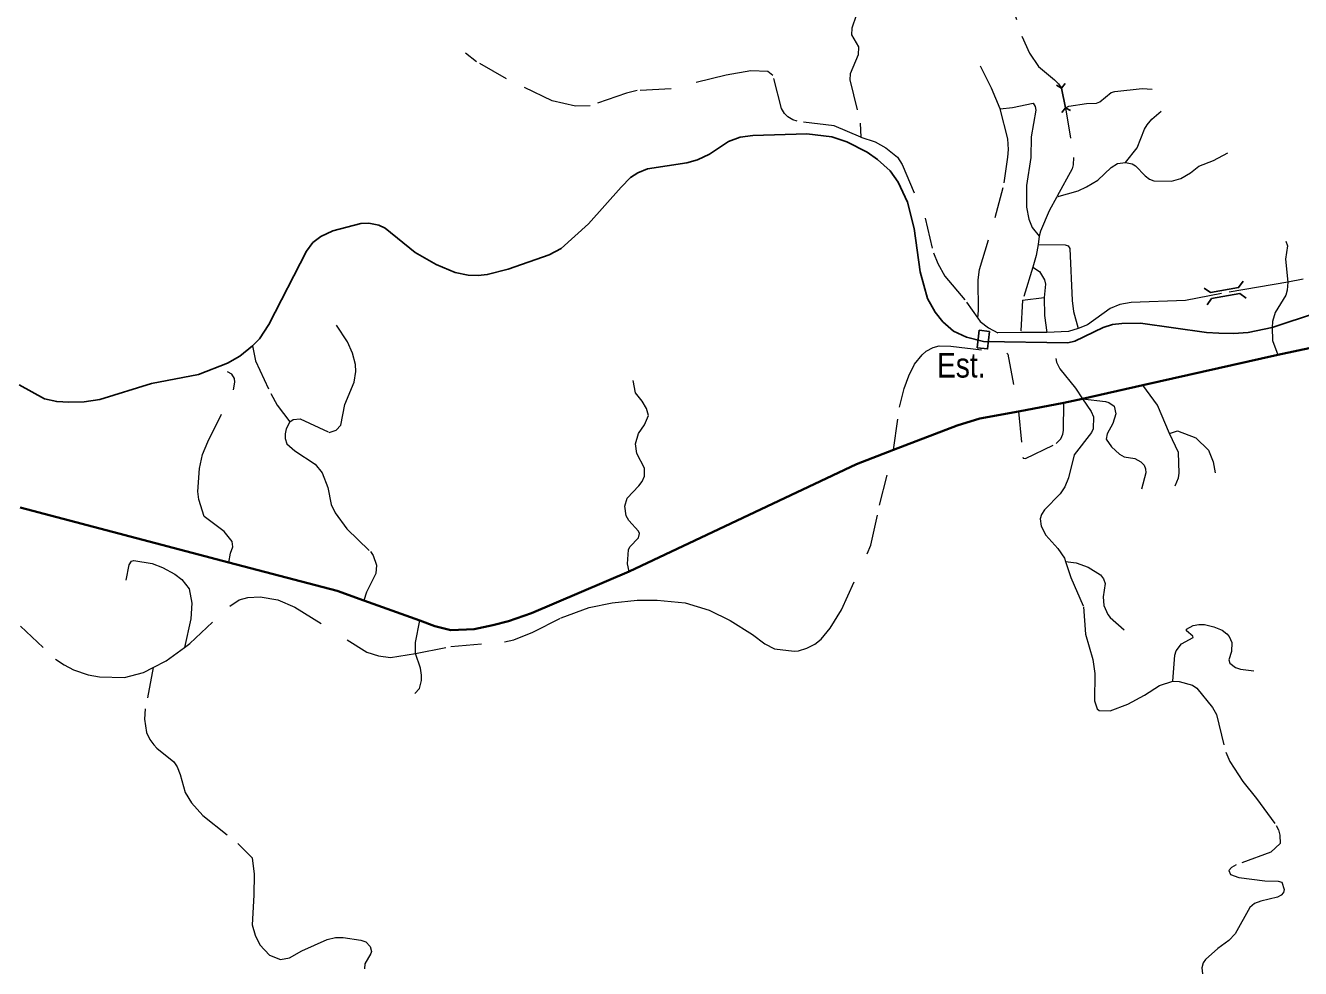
# Model space of a CAD drawing. Extents: x 220.8 to 246.7, y 7287.6 to 7315.8.
# Drawn here: x 235.279 to 239.405, y 7305.147 to 7308.198 of the extents above; entities that cross this region are included whole.
import ezdxf
from ezdxf.enums import TextEntityAlignment as Align

# ---------------------------------------------------------------- set-up
doc = ezdxf.new("R2010")
doc.units = 0
doc.header["$LTSCALE"] = 0.032
for name, pattern in [('DOTTED', [1.5, 0.3, -1.2]), ('LONG_DASHED', [7.5, 6, -1.5]), ('MEDIUM_DASHED', [4.5, 3, -1.5])]:
    doc.linetypes.add(name, pattern=pattern)
for name, color, linetype, lineweight in [('10', 7, 'Continuous', 25), ('15', 7, 'Continuous', 25), ('2', 7, 'Continuous', 35), ('28', 7, 'Continuous', 25), ('31', 7, 'Continuous', 25), ('5', 7, 'LONG_DASHED', 13), ('6', 7, 'MEDIUM_DASHED', 13), ('7', 7, 'DOTTED', 13)]:
    doc.layers.add(name, color=color, linetype=linetype, lineweight=lineweight)
doc.layers.add('61', color=7, linetype='Continuous')

msp = doc.modelspace()

# ---------------------------------------------------------------- linework, layer by layer
at = {"layer": '10'}
for p, q in [((239.1133, 7307.3343), (239.0929, 7307.3487)), ((239.1026, 7307.2942), (239.1168, 7307.3146)), ((239.1168, 7307.3146), (239.2078, 7307.3307)), ((239.2284, 7307.3165), (239.2078, 7307.3307))]:
    msp.add_line(p, q, dxfattribs=at)
msp.add_lwpolyline([(239.1133, 7307.3343), (239.2043, 7307.3504), (239.2187, 7307.371)], dxfattribs=at)
at = {"layer": '15'}
msp.add_lwpolyline([(239.7468, 7307.3643), (239.3125, 7307.2206), (239.235, 7307.2054), (239.188, 7307.2019), (239.1401, 7307.2028), (239.0999, 7307.2045), (238.8872, 7307.2353), (238.8265, 7307.2344), (238.7966, 7307.231), (238.7658, 7307.2207), (238.6744, 7307.1772), (238.6513, 7307.1712), (238.3787, 7307.1763), (238.324, 7307.19), (238.2821, 7307.2096), (238.2471, 7307.2395), (238.2223, 7307.2703), (238.1975, 7307.3147), (238.1736, 7307.4011), (238.1539, 7307.5412), (238.1326, 7307.6267), (238.1027, 7307.6916), (238.077, 7307.7284), (238.036, 7307.7651), (238.0027, 7307.789), (237.9369, 7307.8224), (237.8882, 7307.8386), (237.807, 7307.848), (237.6327, 7307.8429), (237.5916, 7307.8369), (237.554, 7307.8232), (237.4917, 7307.7822), (237.4532, 7307.7642), (237.419, 7307.754), (237.2917, 7307.7343), (237.2601, 7307.7215), (237.237, 7307.7061), (237.2062, 7307.6754), (237.1011, 7307.5566), (237.0123, 7307.4763), (236.9729, 7307.4558), (236.8405, 7307.4096), (236.773, 7307.3925), (236.7439, 7307.3891), (236.7114, 7307.3908), (236.6687, 7307.3993), (236.6072, 7307.425), (236.5397, 7307.4634), (236.4431, 7307.5421), (236.4218, 7307.5523), (236.3893, 7307.5583), (236.3636, 7307.5574), (236.2731, 7307.5335), (236.2346, 7307.5156), (236.209, 7307.4959), (236.1876, 7307.4677), (236.0663, 7307.231), (236.0355, 7307.184), (236.013, 7307.1615), (235.9723, 7307.1285), (235.9329, 7307.1054), (235.8389, 7307.0695), (235.686, 7307.0396), (235.5193, 7306.9883), (235.4681, 7306.9806), (235.4185, 7306.9798), (235.38, 7306.9815), (235.3399, 7306.99), (235.2578, 7307.0353)], dxfattribs=at)
at = {"layer": '2'}
msp.add_lwpolyline([(235.2612, 7306.6381), (235.937, 7306.461), (236.2872, 7306.3691), (236.3741, 7306.3378), (236.5552, 7306.2724), (236.6035, 7306.255), (236.6546, 7306.2419), (236.7307, 7306.2445), (236.7911, 7306.2576), (236.8422, 7306.2707), (236.9157, 7306.297), (237.2323, 7306.4315), (237.968, 7306.7785), (238.088, 7306.825), (238.2934, 7306.9045), (238.3669, 7306.9268), (238.4921, 7306.9497), (238.6391, 7306.9774), (238.699, 7306.9905), (238.6995, 7306.9906), (238.8939, 7307.0343), (239.3316, 7307.1323), (239.6303, 7307.1959)], dxfattribs=at)
at = {"layer": '28'}
msp.add_lwpolyline([(238.3985, 7307.2085), (238.3921, 7307.1519), (238.3584, 7307.1557), (238.3648, 7307.2123)], close=True, dxfattribs=at)
at = {"layer": '31'}
for p, q in [((238.6312, 7307.9957), (238.6428, 7308.0105)), ((238.6151, 7308.0051), (238.6312, 7307.9957)), ((238.6312, 7307.9957), (238.6437, 7307.9321)), ((238.6321, 7307.9174), (238.6437, 7307.9321)), ((238.6437, 7307.9321), (238.6599, 7307.9228))]:
    msp.add_line(p, q, dxfattribs=at)
at = {"layer": '5'}
for points in [[(238.5556, 7307.4901), (238.6431, 7307.4881), (238.6531, 7307.4851), (238.6582, 7307.477), (238.6652, 7307.308), (238.6702, 7307.2728), (238.6854, 7307.218)], [(239.8673, 7307.477), (239.7828, 7307.4479), (239.7003, 7307.4298), (239.3631, 7307.368), (239.1492, 7307.3307), (239.0324, 7307.308), (238.8563, 7307.302), (238.8201, 7307.296), (238.789, 7307.2829), (238.7155, 7307.2296), (238.6854, 7307.218)], [(238.6854, 7307.218), (238.6542, 7307.2085), (238.5836, 7307.2054), (238.4992, 7307.2054), (238.4248, 7307.2034)]]:
    msp.add_lwpolyline(points, dxfattribs=at)
at = {"layer": '6'}
for p, q in [((238.5384, 7307.4168), (238.5055, 7307.3096)), ((238.5055, 7307.3096), (238.4992, 7307.2054)), ((238.5055, 7307.3096), (238.5754, 7307.3181))]:
    msp.add_line(p, q, dxfattribs=at)
for points in [[(238.0208, 7308.4066), (238.0204, 7308.3112), (238.0054, 7308.2784), (237.9666, 7308.2306), (237.9532, 7308.1903), (237.9517, 7308.1686), (237.9748, 7308.129), (237.9733, 7308.1037), (237.9472, 7308.0417), (237.9465, 7308.0223), (237.9801, 7307.8827), (237.9823, 7307.8371)], [(238.4553, 7308.3135), (238.5031, 7308.1644), (238.5272, 7308.109), (238.5573, 7308.0652), (238.6088, 7308.0224), (238.621, 7308.01), (238.6312, 7307.9957), (238.6437, 7307.9321), (238.6702, 7307.7708), (238.6691, 7307.7478), (238.6658, 7307.7341), (238.6159, 7307.6438), (238.5913, 7307.5987), (238.5628, 7307.5324), (238.559, 7307.5165), (238.5556, 7307.4901), (238.5496, 7307.454), (238.5384, 7307.4168)], [(237.9823, 7307.8371), (237.8957, 7307.8737), (237.7762, 7307.8886), (237.7613, 7307.8931), (237.7456, 7307.9028), (237.7344, 7307.914), (237.7254, 7307.9297), (237.6971, 7308.0365), (237.6814, 7308.0492), (237.6254, 7308.0514), (237.5463, 7308.038), (237.3678, 7307.9932), (237.258, 7307.9879), (237.2237, 7307.9797), (237.1057, 7307.9387), (237.0587, 7307.9372), (236.9833, 7307.9543), (236.8354, 7308.0253), (236.7384, 7308.0813), (236.7025, 7308.1089)], [(237.9823, 7307.8371), (238.0278, 7307.8214), (238.0629, 7307.802), (238.1003, 7307.7721), (238.1152, 7307.7483), (238.1899, 7307.575), (238.2168, 7307.4623), (238.2309, 7307.4279), (238.2533, 7307.3869), (238.3243, 7307.3032), (238.3601, 7307.2514), (238.3683, 7307.2405), (238.3945, 7307.2196), (238.4248, 7307.2034)], [(238.5384, 7307.4168), (238.5595, 7307.4025), (238.5765, 7307.3756), (238.5798, 7307.3614), (238.5754, 7307.3181)], [(238.5754, 7307.3181), (238.576, 7307.26), (238.5836, 7307.2054)], [(235.2626, 7306.2541), (235.376, 7306.1482), (235.4036, 7306.1292), (235.4341, 7306.1136), (235.4819, 7306.0975), (235.5181, 7306.0906), (235.5987, 7306.0889), (235.6609, 7306.105), (235.692, 7306.121), (235.7334, 7306.1424), (235.7929, 7306.186), (235.8105, 7306.1988), (235.94, 7306.3197), (235.9699, 7306.3398), (235.9987, 7306.3473), (236.0378, 7306.3496), (236.0948, 7306.3398), (236.1506, 7306.3162), (236.3831, 7306.1706), (236.4206, 7306.1585), (236.4597, 7306.1533), (236.541, 7306.1665), (236.6548, 7306.189), (236.8286, 7306.2034), (236.8591, 7306.2103), (236.9207, 7306.2351), (237.0116, 7306.2811), (237.1031, 7306.3145), (237.1774, 7306.33), (237.2585, 7306.3387), (237.3224, 7306.3387), (237.4139, 7306.33), (237.491, 7306.3064), (237.5589, 7306.2725), (237.6314, 7306.2276), (237.6711, 7306.1971), (237.7028, 7306.181), (237.7661, 7306.1741), (237.7805, 7306.1746), (237.807, 7306.1839), (237.8329, 7306.1965), (237.853, 7306.2126), (237.8824, 7306.2483), (237.9192, 7306.307), (238.0147, 7306.5165), (238.0424, 7306.646), (238.088, 7306.825), (238.1068, 7306.9637), (238.1218, 7307.0241), (238.1373, 7307.0644), (238.1557, 7307.1029), (238.1805, 7307.1323), (238.1931, 7307.145), (238.2162, 7307.1559), (238.2357, 7307.1616), (238.2731, 7307.1611), (238.4538, 7307.1381), (238.4573, 7307.1352), (238.4921, 7306.9497), (238.5062, 7306.8014), (238.5074, 7306.7979), (238.5143, 7306.7968), (238.6144, 7306.8457), (238.6288, 7306.8607), (238.6357, 7306.8756), (238.6374, 7306.8883), (238.6391, 7306.9774)], [(238.6124, 7307.1211), (238.6146, 7307.109), (238.626, 7307.087), (238.676, 7307.0248), (238.6989, 7306.9907), (238.699, 7306.9905), (238.7268, 7306.9498), (238.7344, 7306.9324), (238.7336, 7306.8929), (238.7283, 7306.8808), (238.6722, 7306.8088), (238.6541, 7306.7345), (238.6419, 7306.7057), (238.6268, 7306.683), (238.576, 7306.6315), (238.5661, 7306.6163), (238.5623, 7306.6019), (238.5654, 7306.5784), (238.5805, 7306.5489), (238.6192, 7306.5057), (238.6404, 7306.4746), (238.6439, 7306.4639), (238.6609, 7306.4117), (238.7026, 7306.3169), (238.7094, 7306.229), (238.7329, 7306.1472), (238.7389, 7306.1009), (238.7381, 7306.0127), (238.7465, 7305.9872), (238.7526, 7305.9819), (238.7882, 7305.9804), (238.8458, 7306.0024), (238.8996, 7306.0312), (238.9481, 7306.063), (238.991, 7306.0768), (239.0125, 7306.0752), (239.055, 7306.0638), (239.0694, 7306.0539), (239.1194, 7305.991), (239.1331, 7305.9683), (239.1626, 7305.8463), (239.1755, 7305.8167), (239.2179, 7305.7523), (239.2627, 7305.697), (239.3256, 7305.6098), (239.3339, 7305.5954), (239.3377, 7305.578), (239.3385, 7305.5514), (239.3089, 7305.5234), (239.1967, 7305.4825), (239.1808, 7305.4741), (239.1732, 7305.4635), (239.1778, 7305.4514), (239.2051, 7305.4408), (239.2892, 7305.4309), (239.3324, 7305.4294), (239.3438, 7305.4256), (239.3513, 7305.4029), (239.3498, 7305.3923), (239.3422, 7305.3839), (239.3301, 7305.3771), (239.2763, 7305.3642), (239.2558, 7305.3566), (239.2407, 7305.3445), (239.1937, 7305.2589), (239.1725, 7305.2369), (239.1368, 7305.2119), (239.0967, 7305.1763), (239.0891, 7305.1649), (239.0853, 7305.149), (239.0876, 7305.13)]]:
    msp.add_lwpolyline(points, dxfattribs=at)
at = {"layer": '7'}
for points in [[(238.4326, 7307.9288), (238.4049, 7307.9961), (238.3691, 7308.0663)], [(238.6437, 7307.9321), (238.6551, 7307.937), (238.7122, 7307.9463), (238.7441, 7307.9468), (238.7548, 7307.9513), (238.7923, 7307.9815), (238.804, 7307.9849), (238.8919, 7307.995), (238.9244, 7307.9927)], [(238.3601, 7307.2514), (238.3631, 7307.2764), (238.3616, 7307.3757), (238.3661, 7307.4093), (238.4169, 7307.5773), (238.446, 7307.6893), (238.4572, 7307.7721), (238.4594, 7307.7968), (238.4572, 7307.8319), (238.4326, 7307.9288)], [(238.4326, 7307.9288), (238.4729, 7307.9334), (238.5393, 7307.9469), (238.546, 7307.9364), (238.5483, 7307.9245), (238.5326, 7307.8379), (238.5318, 7307.7707), (238.5184, 7307.6811), (238.5177, 7307.6101), (238.5251, 7307.5713), (238.5363, 7307.5444), (238.559, 7307.5165)], [(238.8387, 7307.7548), (238.8757, 7307.8024), (238.8998, 7307.8634), (238.9081, 7307.8768), (238.9238, 7307.8953), (238.9535, 7307.9216)], [(238.8387, 7307.7548), (238.86, 7307.7503), (238.8706, 7307.7447), (238.902, 7307.7123), (238.916, 7307.7016), (238.9305, 7307.6955), (238.9871, 7307.6949), (239.0173, 7307.7028), (239.0486, 7307.7218), (239.0755, 7307.7436), (239.1231, 7307.7615), (239.1696, 7307.7862)], [(238.6159, 7307.6438), (238.6854, 7307.6636), (238.7122, 7307.6759), (238.7486, 7307.6983), (238.7917, 7307.7386), (238.8124, 7307.752), (238.8387, 7307.7548)], [(239.3572, 7307.5009), (239.3624, 7307.4855), (239.3565, 7307.4418), (239.3631, 7307.368), (239.3614, 7307.3415), (239.3568, 7307.3255), (239.3229, 7307.2699), (239.3135, 7307.2409), (239.3125, 7307.2206), (239.3138, 7307.1787), (239.3316, 7307.1323)], [(236.1344, 7306.9159), (236.1449, 7306.923), (236.1676, 7306.9251), (236.2616, 7306.8815), (236.2839, 7306.889), (236.2986, 7306.905), (236.3116, 7306.9722), (236.3426, 7307.044), (236.3481, 7307.0784), (236.3468, 7307.1015), (236.3368, 7307.1384), (236.3204, 7307.175), (236.2855, 7307.2283)], [(236.013, 7307.1615), (236.0231, 7307.1137), (236.0731, 7307.007), (236.0928, 7306.9697), (236.1344, 7306.9159)], [(235.937, 7306.461), (235.9424, 7306.4913), (235.9501, 7306.5109), (235.9477, 7306.5285), (235.9213, 7306.5609), (235.8573, 7306.6094), (235.8392, 7306.665), (235.8368, 7306.6903), (235.8419, 7306.7643), (235.852, 7306.8101), (235.8692, 7306.8512), (235.9513, 7307.0198), (235.9564, 7307.0445), (235.9546, 7307.0561), (235.946, 7307.0703), (235.9326, 7307.0772)], [(237.2323, 7306.4315), (237.2273, 7306.4561), (237.2299, 7306.5013), (237.2348, 7306.5108), (237.2625, 7306.5407), (237.2652, 7306.554), (237.2622, 7306.562), (237.2311, 7306.5961), (237.2223, 7306.6113), (237.2178, 7306.6428), (237.2257, 7306.669), (237.2637, 7306.7092), (237.2747, 7306.7232), (237.2815, 7306.7395), (237.2823, 7306.7664), (237.2565, 7306.8131), (237.2523, 7306.8446), (237.2629, 7306.878), (237.2819, 7306.9061), (237.2948, 7306.9364), (237.2887, 7306.9588), (237.2743, 7306.9831), (237.2527, 7307.0096), (237.2451, 7307.0498)], [(238.9802, 7306.8781), (238.942, 7306.9695), (238.8939, 7307.0343)], [(238.6989, 7306.9907), (238.6995, 7306.9906), (238.7735, 7306.982), (238.7844, 7306.9784), (238.8016, 7306.9664), (238.8073, 7306.942), (238.7974, 7306.9102), (238.7787, 7306.8769), (238.7756, 7306.8593), (238.7927, 7306.8348), (238.8187, 7306.8114), (238.8338, 7306.8026), (238.8687, 7306.7968), (238.8879, 7306.7869), (238.8983, 7306.7755), (238.9035, 7306.7635), (238.9046, 7306.7505), (238.89, 7306.698)], [(236.1344, 7306.9159), (236.1222, 7306.8937), (236.1192, 7306.8775), (236.119, 7306.8615), (236.1249, 7306.845), (236.1503, 7306.8218), (236.2165, 7306.7788), (236.2392, 7306.7507), (236.2576, 7306.7029), (236.2676, 7306.6488), (236.2809, 7306.6209), (236.319, 7306.5693), (236.3949, 7306.4958), (236.4036, 7306.4831), (236.4147, 7306.4515), (236.4128, 7306.4247), (236.3825, 7306.3642), (236.3741, 7306.3378)], [(238.9802, 7306.8781), (239.007, 7306.8865), (239.0654, 7306.8642), (239.1064, 7306.8239), (239.122, 7306.7859), (239.1288, 7306.7505)], [(238.9992, 7306.7084), (239.0096, 7306.7344), (239.0122, 7306.7495), (239.0096, 7306.8161), (238.9802, 7306.8781)], [(235.605, 7306.4037), (235.6147, 7306.4529), (235.622, 7306.465), (235.6292, 7306.4674), (235.689, 7306.4569), (235.7221, 7306.4448), (235.7624, 7306.423), (235.7842, 7306.4061), (235.8084, 7306.3754), (235.8165, 7306.3286), (235.8133, 7306.2785), (235.7929, 7306.186)], [(238.6439, 7306.4639), (238.6786, 7306.4593), (238.7176, 7306.4455), (238.7577, 7306.4203), (238.7667, 7306.4078), (238.7727, 7306.3922), (238.7661, 7306.3496), (238.7679, 7306.322), (238.7811, 7306.2926), (238.7889, 7306.2824), (238.8335, 7306.2423)], [(236.5391, 7306.0372), (236.554, 7306.053), (236.5603, 7306.0784), (236.5606, 7306.0962), (236.5564, 7306.1192), (236.541, 7306.1665), (236.5404, 7306.2012), (236.5552, 7306.2724)], [(238.991, 7306.0768), (238.9978, 7306.1603), (239.0019, 7306.1745), (239.0192, 7306.1969), (239.0568, 7306.2176), (239.0558, 7306.2227), (239.0361, 7306.2393), (239.0354, 7306.2444), (239.0568, 7306.2566), (239.0755, 7306.2603), (239.0941, 7306.2596), (239.1239, 7306.2525), (239.1511, 7306.242), (239.1667, 7306.2295), (239.1741, 7306.2213), (239.1823, 7306.2017), (239.1812, 7306.1722), (239.1731, 7306.1454), (239.1762, 7306.1352), (239.1948, 7306.1213), (239.2104, 7306.1152), (239.2531, 7306.1101)], [(235.692, 7306.121), (235.6661, 7305.9866), (235.6636, 7305.9536), (235.6707, 7305.9103), (235.6807, 7305.8881), (235.6936, 7305.871), (235.7041, 7305.8593), (235.7587, 7305.8151), (235.7696, 7305.7993), (235.7796, 7305.7746), (235.7959, 7305.7158), (235.8155, 7305.6832), (235.8531, 7305.6424), (235.9661, 7305.5518), (236.012, 7305.5051), (236.0187, 7305.4525), (236.0179, 7305.3836), (236.012, 7305.2881), (236.0221, 7305.2547), (236.0375, 7305.2234), (236.0688, 7305.19), (236.1038, 7305.1758), (236.1335, 7305.1808), (236.1731, 7305.2034), (236.2545, 7305.2405), (236.2824, 7305.2476), (236.3062, 7305.2476), (236.3638, 7305.2388), (236.3801, 7305.233), (236.3943, 7305.2175), (236.398, 7305.2021), (236.3964, 7305.1954), (236.3763, 7305.162), (236.3755, 7305.1458)]]:
    msp.add_lwpolyline(points, dxfattribs=at)

# ---------------------------------------------------------------- texts
at = {"layer": '61', "width": 0.85}
msp.add_text('Est.', height=0.08, dxfattribs=at).set_placement((238.3852, 7307.0591), align=Align.RIGHT)

doc.saveas('drawing.dxf')
